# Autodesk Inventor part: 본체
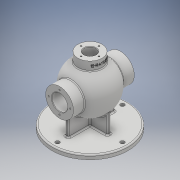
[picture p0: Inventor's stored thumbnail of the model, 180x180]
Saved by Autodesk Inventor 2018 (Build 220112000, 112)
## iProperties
Created: 2020-08
Part Number: 본체
Material: 일반
Document SubType Name: Modeling
Designer: USER
Density: 1 g/cm^3
Appearance: 기본값
Mass: 625.897 g
Surface Area: 1351.62 cm^2
Volume: 625.897 cm^3
Author: USER
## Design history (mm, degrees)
sketch "스케치1"
  geometry: C1 r 85 at (0, 0); 1 further point
  constraints: 1 centre point, 1 coincident
  dimensions: "d0" = 170 diameter of C1
extrude "돌출1" new body sketch "스케치1" distance "d1" = 10; taper "d2" = 0 deg
sketch "스케치14"
  geometry: L1 (85, 10)-(-85, 10) reference; L2 (-85, 0)-(85, 0) reference; L3 (-68, 116)-(-68, 54) reference; L4 (-68, 85)-(-87.497, 85); L5 (0, 85)-(0, 138); L6 (0, 85)-(53, 85); A1 r 53 centre (0, 85) between (53, 85) and (0, 138); 2 further points
  constraints: 6 end point, 2 horizontal, 2 midpoint, 2 point on circle, 1 centre point, 1 vertical, 1 vertical alignment
  dimensions: "d32" = 106 diameter of A1; "d33" = 85 distance from line of L2 L5.start
revolve "회전2" sketch "스케치14" stored, may be unused: angle "d34" = 110 deg
sketch "스케치15"
  geometry: 1 further point
sketch "스케치17"
  geometry: L1 (85, 10)-(-85, 10) reference; L2 (-85, 0)-(85, 0) reference; C1 r 53 at (0, 85) reference; C2 r 31 at (0, 85); 1 further point
  constraints: 1 centre point, 1 coincident
  dimensions: "d36" = 62 diameter of C2
extrude "돌출3" join sketch "스케치17" stored distance "d37" = 136; taper "d38" = 0 deg
sketch "스케치18"
  geometry: L1 (-68, 116)-(-68, 54) reference; L2 (68, 54)-(68, 116) reference; L3 (42.988, 116)-(42.988, 54) reference; L4 (-68, 85)-(-84.831, 85); L5 (-68, 85)-(-68, 102.5); L6 (68, 54)-(68, 116) reference; L7 (-68, 85)-(68, 85); L8 (68, 85)-(68, 102.5); L9 (68, 102.5)-(52, 102.5); L10 (52, 102.5)-(52, 103.5); L11 (52, 103.5)-(50.25, 103.5); L12 (50.25, 103.5)-(50.25, 102.5); L13 (50.25, 102.5)-(-68, 102.5); 1 further point
  constraints: 18 end point, 4 perpendicular, 3 point on line, 2 horizontal, 2 midpoint, 1 collinear
  dimensions: "d116" = 16 distance of L8.end L9.end; "d117" = 35 diameter of L9 L4; "d118" = 37 diameter of L11 L4; "d119" = 1.75 distance of L10.end L11.end
revolve "회전3" sketch "스케치18" stored, may be unused: angle "d43" = 110 deg
sketch "스케치19"
  geometry: L1 (42.988, 116)-(42.988, 54) reference; L2 (-42.988, 54)-(-42.988, 116) reference; L3 (-68, 116)-(-68, 54) reference; L4 (-68, 85)-(-90.571, 85); L5 (-85, 0)-(85, 0) reference; L6 (0, 86.324)-(0, 129.324); L7 (0, 86.324)-(43, 86.324); A1 r 43 centre (0, 86.324) between (42.988, 85.324) and (0, 129.324); A2 r 43 centre (0, 86.324) between (-42.988, 87.324) and (-42.988, 85.324); 2 further points
  constraints: 6 end point, 5 point on circle, 3 point on line, 2 centre point, 2 horizontal, 2 midpoint, 1 vertical, 1 vertical alignment
  dimensions: "d45" = 86.32362 distance from line of L5 L6.start; "d46" = 43 radius of A1
revolve "회전4" sketch "스케치19" stored, may be unused: angle "d47" = 110 deg
node "작업 평면2"
sketch "스케치22"
  geometry: L1 (-31, 42.988)-(31, 42.988) reference; L2 (31, -42.988)-(-31, -42.988) reference; C1 r 27 at (0, 0); 1 further point
  constraints: 1 centre point, 1 coincident
  dimensions: "d49" = 54 diameter of C1
extrude "돌출4" join sketch "스케치22" stored distance "d50" = 136; taper "d51" = 0 deg
sketch "스케치23"
  geometry: C1 r 27 at (0, 0) reference; C2 r 13 at (0, 0); 1 further point
  constraints: 1 centre point, 1 coincident
  dimensions: "d52" = 26 diameter of C2
extrude "돌출5" cut sketch "스케치23" distance "d53" = 60; taper "d54" = 0 deg
sketch "스케치24"
  geometry: C1 r 13 at (0, 0) reference; C2 r 27 at (0, 0) reference; A1 r 20 centre (0, 0) between (0, 20) and (20, 0); 3 further points
  constraints: 4 point on circle, 2 horizontal alignment, 2 vertical alignment, 1 centre point, 1 coincident
  dimensions: "d55" = 40 diameter of A1
hole "구멍1" sketch "스케치24" at (-20, 0), (0, -20), (20, 0), (0, 20) diameter "d56" = 3.242; stored, may be unused: countersink angle "d60" = 90 deg, drill point angle "d62" = 118 deg; dims "d57" = 12, "d58" = 4, "d59" = 2, "d61" = 15
sketch "스케치25"
  geometry: C1 r 85 at (0, 0) reference; C2 r 4.5 at (0, 72.5); C3 r 4.5 at (-72.5, 0); C4 r 4.5 at (0, -72.5); C5 r 4.5 at (72.5, 0); A1 r 72.5 centre (0, 0) between (0, 72.5) and (-72.5, 0); 1 further point
  constraints: 5 centre point, 4 point on circle, 2 horizontal alignment, 2 vertical alignment, 1 coincident
  dimensions: "d63" = 145 diameter of A1; "d64" = 9 diameter of C2; "d65" = 9 diameter of C3; "d66" = 9 diameter of C4; "d67" = 9 diameter of C5
extrude "돌출6" cut sketch "스케치25" distance "d68" = 60; taper "d69" = 0 deg
sketch "스케치28"
  geometry: L1 (85, 10)-(-85, 10) reference; L2 (-85, 0)-(85, 0) reference; L3 (-68, 54)-(-42.988, 54) reference; L4 (85, 10)-(-85, 10) reference; L5 (-52, 10)-(-52, 54); L6 (0, 10)-(0, 32); L7 (0, 10)-(-52, 10); A1 r 53 centre (0, 85) between (42.988, 116) and (42.988, 54) reference; 1 further point
  constraints: 6 end point, 2 point on line, 1 collinear, 1 midpoint, 1 perpendicular, 1 point on circle, 1 vertical
  dimensions: "d77" = 52 distance of L6.start L5.start
feature "리브1" sketch "스케치28" dims "d78" = 1, "d79" = 8, "d80" = 0, "d81" = 0, "d82" = 1, "d83" = 1
sketch "스케치29"
  geometry: L1 (85, 10)-(-85, 10) reference; L2 (4, 10)-(4, 54.259) reference; L3 (0, 10)-(4, 10); L4 (4, 10)-(43, 10); L5 (43, 10)-(43, 54.016); A1 r 53 centre (0, 85) between (-27, 130.607) and (27, 130.607) reference; 1 further point
  constraints: 6 end point, 1 collinear, 1 midpoint, 1 point on circle, 1 point on line, 1 vertical
  dimensions: "d85" = 4 distance of L3.start L2.start (derived); "d86" = 39 distance of L2.start L4.end
feature "리브2" sketch "스케치29" dims "d87" = 1, "d88" = 8, "d89" = 0, "d90" = 0, "d91" = 1, "d92" = 1
fillet "모깎기1" dims "d93" = 3
fillet "모깎기2" dims "d94" = 3
fillet "모깎기3" dims "d95" = 3
fillet "모깎기4" dims "d96" = 3
chamfer "모따기1" distance "d97" = 1; stored, may be unused: second distance "d98" = 2, angle "d99" = 45 deg
sketch "스케치30"
  geometry: C1 r 31 at (0, 0) reference; A1 r 24 centre (0, 0) between (0, 24) and (24, 0); 3 further points
  constraints: 4 point on circle, 2 horizontal alignment, 2 vertical alignment, 1 centre point
  dimensions: "d106" = 48 diameter of A1
hole "구멍2" sketch "스케치30" at (0, 24), (24, 0), (0, -24), (-24, 0) diameter "d107" = 3.242; stored, may be unused: countersink angle "d111" = 90 deg, drill point angle "d113" = 118 deg; dims "d108" = 12, "d109" = 4, "d110" = 2, "d112" = 15
node "작업 평면4"
sketch "스케치31"
  geometry: 2 further points
  constraints: 1 other
feature "엠보싱1" sketch "스케치31" dims "d114" = 0.5, "d115" = 0
chamfer "모따기4" distance "d120" = 1; stored, may be unused: second distance "d121" = 2, angle "d122" = 45 deg
chamfer "모따기5" distance "d123" = 1; stored, may be unused: second distance "d124" = 2, angle "d125" = 45 deg
node "솔리드1"
mirror "미러1"
mirror "미러2"
mirror "미러3"
mirror "미러4"
mirror "미러5"
node "투영된 루프7"
node "작업 평면1"
node "투영된 루프9"
node "투영된 루프10"
node "투영된 루프11"
node "투영된 루프12"
node "투영된 루프13"
node "투영된 루프14"
node "투영된 루프15"
node "투영된 루프17"
node "작업 평면3"
node "투영된 루프18"
other parameters: "d44" = 86
